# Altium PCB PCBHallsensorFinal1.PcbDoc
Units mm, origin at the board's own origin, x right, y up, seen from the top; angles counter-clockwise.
Board outline 40 x 30 mm, 2 copper layers (Top Layer, Bottom Layer); 4 components, 8 nets, 27 pads, 11 vias.
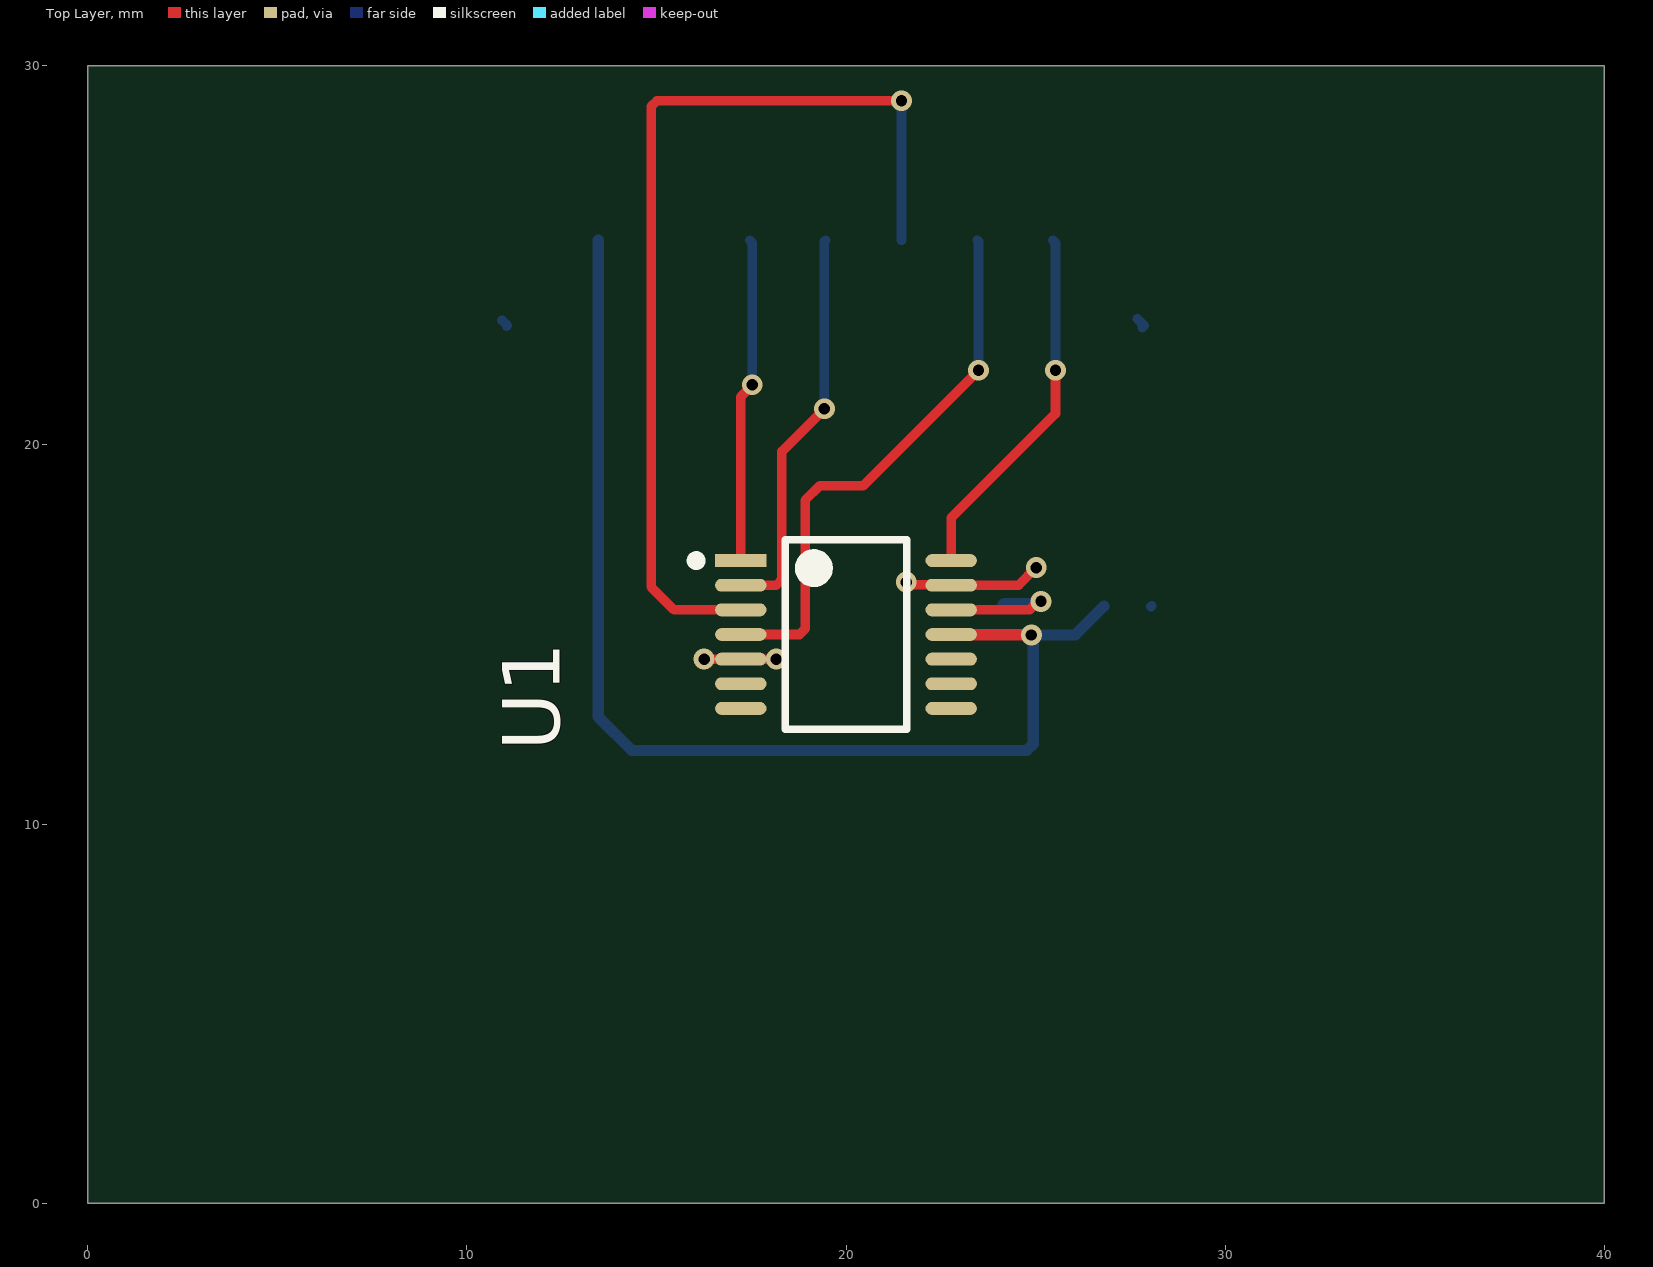
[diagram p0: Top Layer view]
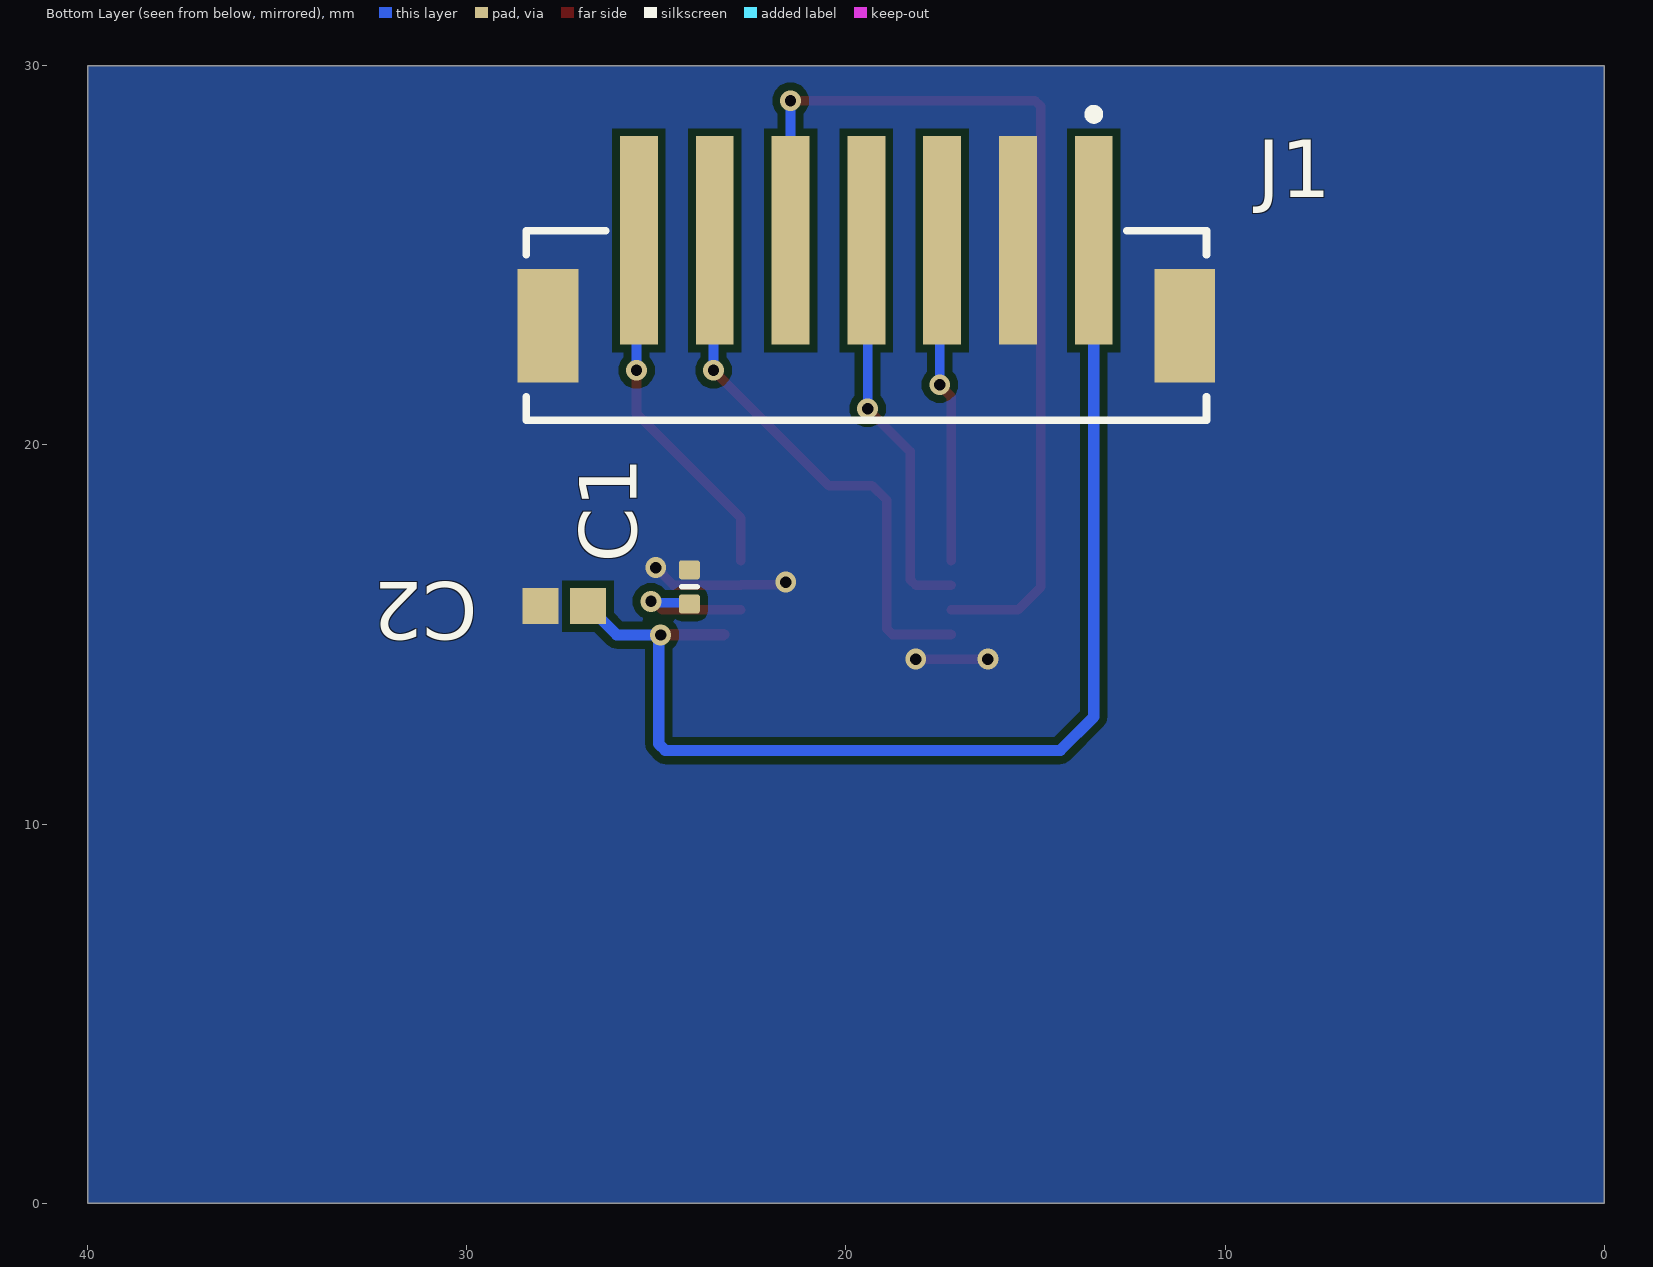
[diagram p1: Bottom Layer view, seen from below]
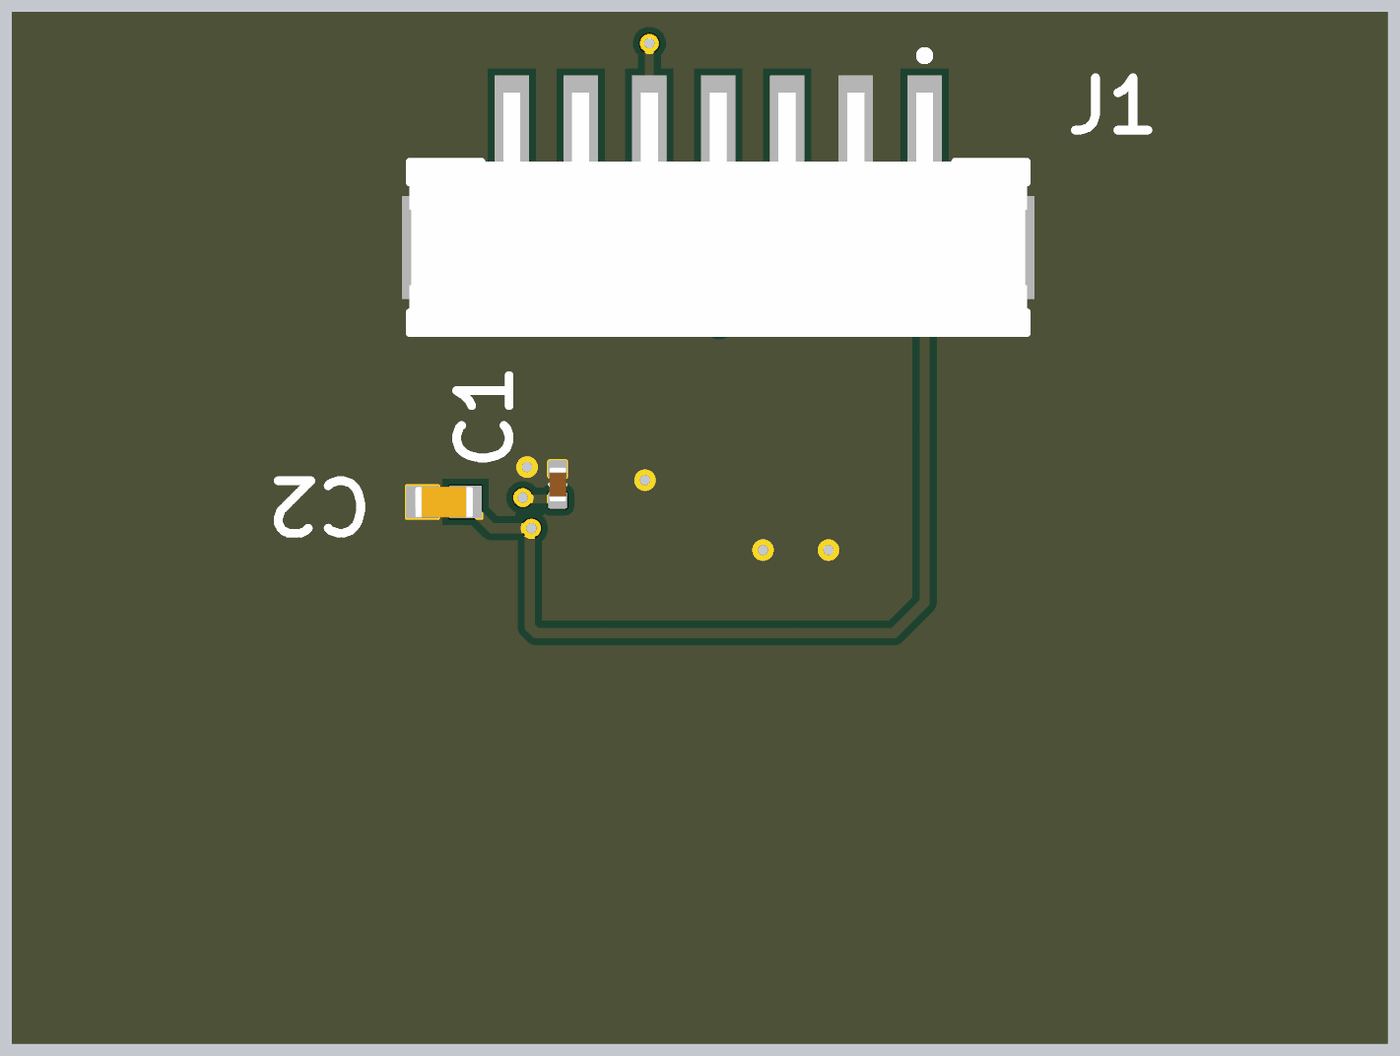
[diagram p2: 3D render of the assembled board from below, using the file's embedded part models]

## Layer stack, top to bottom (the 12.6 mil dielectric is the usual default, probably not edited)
Top Solder: solder mask 0.0102, Solder Resist, Dk 3.5
Top Layer: signal copper 0.0356
Dielectric 1: dielectric 0.32, FR-4, Dk 4.8
Bottom Layer: signal copper 0.0356
Bottom Solder: solder mask 0.0102, Solder Resist, Dk 3.5

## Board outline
0,0 0,30 40,30 40,0

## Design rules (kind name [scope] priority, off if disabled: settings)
Clearance [All] p1: gap=0.2 ignorepadtopadclearanceinfootprint=FALSE except(0.125: Arc-Arc Arc-Track Track-Track; 0.15: Arc-Text Track-Text SMDPad-SMDPad SMDPad-Text THPad-Text Via-Text Fill-Text Poly-Text Region-Text Text-Text; 0.18: Arc-SMDPad Track-SMDPad; 0.35: Arc-THPad Track-THPad SMDPad-THPad; 0.45: THPad-THPad THPad-Via)
HoleSize NPTH-HoleSize [IsPad AND (HoleDiameter > 0) AND (PadIsPlated = 'False')] p1: absolutevalues=TRUE maxlimit=6.3 minlimit=0.15 maxpercent=80.000 minpercent=20.000
HoleSize PTH-HoleSize [IsPad AND (HoleDiameter > 0) AND (PadIsPlated = 'True')] p2: absolutevalues=TRUE maxlimit=6.3 minlimit=0.15 maxpercent=80.000 minpercent=20.000
HoleSize Via-HoleSize [IsVia] p3: absolutevalues=TRUE maxlimit=0.3 minlimit=0.15 maxpercent=80.000 minpercent=20.000
HoleToHoleClearance "PTH Spacing" [All] p1: gap=0.45 allowstackedmicrovias=TRUE
HoleToHoleClearance "Via Spacing" [isVia] p2: gap=0.2 allowstackedmicrovias=TRUE
MinimumAnnularRing Via-AnnularRing [IsVia] p1: minimumring=0.1
MinimumSolderMaskSliver [All] p1: minsoldermaskwidth=0.1
PlaneConnect [All] p1: planeconnectstyle=Direct reliefexpansion=0.508 reliefentries=4 reliefconductorwidth=0.254 reliefairgap=0.254
PolygonConnect [All] p1: connectstyle=Direct reliefconductorwidth=0.254 reliefentries=4 polygonreliefangle="90 Angle" airgapwidth=0.254
RoutingVias [IsVia] p1: holewidth=0.3 width=0.25 viastyle="Through Hole" minholewidth=0.15 minwidth=0.25 maxholewidth=0.4 maxwidth=0.55
SilkToSilkClearance [All] p1: silktosilkclearance=0.2
SilkToSolderMaskClearance [IsPad AND ISVIA] p1: minsilkscreentomaskgap=0.15 clearancetoexposedcopper=TRUE
SolderMaskExpansion [All] p1: expansion=0.038 istentingtop=FALSE
SupplyNets "Schematic Supply Nets_5" [InNet('+12V')] p1: voltage=0.000
SupplyNets "Schematic Supply Nets_4" [InNet('GND')] p2: voltage=0.000
SupplyNets "Schematic Supply Nets_3" [InNet('+5V')] p3: voltage=0.000
SupplyNets "Schematic Supply Nets_1" [InNet('-12V')] p4: voltage=0.000
SupplyNets "Schematic Supply Nets" [InNet('-5V')] p5: voltage=0.000
Width [All] p1: maxlimit=10 minlimit=0.1 preferedwidth=0.254 minimp=50.000000 maximp=50.000000 favimp=50.000000
24 further rules are at their usual default settings.

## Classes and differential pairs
component class Encoder_Schemativ: C1 C2 U1

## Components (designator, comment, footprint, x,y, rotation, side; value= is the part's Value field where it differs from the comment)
C1 "Capacitor 470nF +/-40% 10V 0402" CAPC0402(1005)60_L 24.13,16.256 r90 bottom value=10uF
C2 "Capacitor 100 nF +/-10% 50 V 0603" CAPC1608X90X40NL10T20 27.432,15.748 r0 bottom value=100nF
J1 "B7B-PH-SM4-TB(LF)(SN)" FP-B7B-PH-SM4-TB_LF_SN-MFG 19.463,23.15 r0 bottom
U1 "AS5048A-HTSP-500" FP-AS5048A-HTSP-500-IPC_C 20,15 r0 top

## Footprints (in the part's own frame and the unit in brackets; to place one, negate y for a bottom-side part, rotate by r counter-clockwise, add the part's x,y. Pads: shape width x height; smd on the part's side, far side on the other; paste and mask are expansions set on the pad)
CAPC0402(1005)60_L [mm] "Chip Capacitor, Body 1.0x0.5mm, Height 0.6mm, IPC High Density"
  rrect25% 0.5x0.55 smd: 1(-0.45,0) 2(0.45,0)
  silkscreen extent 0,-0.2 0,0.2, body extent -0.5,-0.25 0.5,0.25, height 0.6
CAPC1608X90X40NL10T20 [mm] "Chip Capacitor, 2-Leads, Body 1.70x0.90mm, IPC Medium Density"
  rect 0.95x0.95 smd: 1(-0.625,0) 2(0.625,0)
  body extent -0.85,-0.45 0.85,0.45, height 0.9
FP-AS5048A-HTSP-500-IPC_C [mm]
  rect 1.355x0.341 smd paste+0 mask+0: 1(-2.775,1.95)
  rrect100% 1.355x0.341 smd paste+0 mask+0: 2(-2.775,1.3) 3(-2.775,0.65) 4(-2.775,0) 5(-2.775,-0.65) 6(-2.775,-1.3) 7(-2.775,-1.95) 8(2.775,-1.95) 9(2.775,-1.3) 10(2.775,-0.65) 11(2.775,0) 12(2.775,0.65) 13(2.775,1.3) 14(2.775,1.95)
  silkscreen extent -4.08,-2.5 1.6,2.5
FP-B7B-PH-SM4-TB_LF_SN-MFG [mm]
  rect 1x5.5 smd paste+0 mask+0: 1(-6,-2.25) 2(-4,-2.25) 3(-2,-2.25) 4(0,-2.25) 5(2,-2.25) 6(4,-2.25) 7(6,-2.25)
  rect 1.6x3 smd paste+0 mask+0: 8(-8.4,0) 9(8.4,0)
  silkscreen extent -8.98,-5.7 8.98,2.5, body extent -8.98,-4.5 8.97,2.5, height 6.61

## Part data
C1: library part CMP-001-00060-4, "Chip Capacitor, 470nF +/-40%, 10V, 0402, Thickness 0.6 mm", Case/Package=0402, Max Operating Temperature=85°C, Min Operating Temperature=-55°C, Tolerance=20%, Voltage Rating=10V
C2: library part CMP-001-00017-6, "Chip Capacitor, 100 nF, +/- 10%, 50 V, 0603 (1608 Metric)", Capacitor Type=Ceramic, Case/Package=0603, Max Operating Temperature=125°C, Min Operating Temperature=-55°C, Tolerance=10%, Voltage Rating=50V
J1: library part CMP-17439-000233-1, "CONN HEADER SMD 7POS 2MM", Color=White, Contact Resistance=20mR, Current Rating=2A, Flammability Rating="UL94 V-0", Housing Color=Beige, Insulation Color=Natural, Insulation Resistance=1GR, Max Operating Temperature=85°C, Max Voltage Rating (AC)=100V, Min Operating Temperature=-25°C
U1: library part CMP-22826-000004-1, "SENSOR ANGLE 360DEG SMD", Case/Package=TSSOP, Max Operating Temperature=150°C, Max Supply Voltage=5.5V, Min Operating Temperature=-40°C, Min Supply Voltage=4.5V, Operating Supply Current=15mA, Package Quantity=500

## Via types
v1: diameter 0.55, hole 0.3, Top Layer to Bottom Layer, 11 vias

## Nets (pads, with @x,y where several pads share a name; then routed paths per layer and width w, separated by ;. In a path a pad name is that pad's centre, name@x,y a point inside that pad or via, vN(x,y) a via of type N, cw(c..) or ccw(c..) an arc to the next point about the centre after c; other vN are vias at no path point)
GND: C1.2 C2.2 J1.2 J1.8 J1.9 U1.5 U1.13 | length 6.1
  Top Layer w0.254: v1(16.257,14.35) U1.5 ; U1.5@17.225,14.35 v1(18.161,14.351) ; v1(21.59,16.383) 21.67,16.383 21.736,16.317 22.759,16.317 U1.13 24.555,16.3 v1(25.019,16.764)
  Bottom Layer w0.254: J1.8@10.922,23.291 J1.8 J1.8@11.049,23.136 ; J1.9@27.686,23.327 J1.9 J1.9@27.813,23.1 ; C2.2@28.047,15.738 C2.2 C2.2@28.067,15.758
NetC1_1: C1.1 U1.12 | length 3.5
  Top Layer w0.254: U1.12 24.841,15.65 25.066,15.875 v1(25.146,15.875)
  Bottom Layer w0.254: C1.1 24.164,15.84 25.111,15.84 v1(25.146,15.875)
SPI_CLK: J1.4 U1.2 | length 10.6
  Top Layer w0.254: U1.2 18.16,16.3 18.309,16.449 18.309,19.833 v1(19.431,20.955)
  Bottom Layer w0.254: v1(19.431,20.955) 19.431,25.368 J1.4
SPI_CS: J1.3 U1.1 | length 8.6
  Top Layer w0.254: U1.1 17.225,21.276 17.526,21.578 v1(17.526,21.59)
  Bottom Layer w0.254: J1.3 17.526,25.337 v1(17.526,21.59)
SPI_MISO: J1.5 U1.3 | length 25.6
  Top Layer w0.254: U1.3 15.465,15.65 14.859,16.256 14.859,28.934 15.008,29.083 v1(21.463,29.083)
  Bottom Layer w0.254: J1.5 v1(21.463,29.083)
SPI_MOSI: J1.6 U1.4 | length 14.6
  Top Layer w0.254: U1.4 18.774,15 18.923,15.149 18.923,18.542 19.304,18.923 20.447,18.923 v1(23.495,21.971)
  Bottom Layer w0.254: J1.6 23.495,25.368 v1(23.495,21.971)
SPI_PWM: J1.7 U1.14 | length 9.6
  Top Layer w0.254: U1.14 22.775,18.076 25.527,20.828 v1(25.527,21.971)
  Bottom Layer w0.254: J1.7 25.527,25.336 v1(25.527,21.971)
VDD5V: C2.1 J1.1 U1.11 | length 31.3
  Top Layer w0.3: U1.11@23.227,15 23.234,14.993 24.885,14.993 v1(24.892,14.986)
  Bottom Layer w0.3: J1.1 13.463,12.826 14.351,11.938 24.765,11.938 24.941,12.114 24.941,14.937 v1(24.892,14.986) 26.045,14.986 C2.1
pads on no net: U1.6 U1.7 U1.8 U1.9 U1.10

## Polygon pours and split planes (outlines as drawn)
GND on Bottom Layer "Bot_GND_Fill" (solid, pour order 0): 0,0 0,30 40,30 40,0

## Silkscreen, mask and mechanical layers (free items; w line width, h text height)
Mechanical 1:
  the board outline again, w0.254
Top Top Top Designator:
  lines w3.2: 5,5 5,25 ; 35,5 35,25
